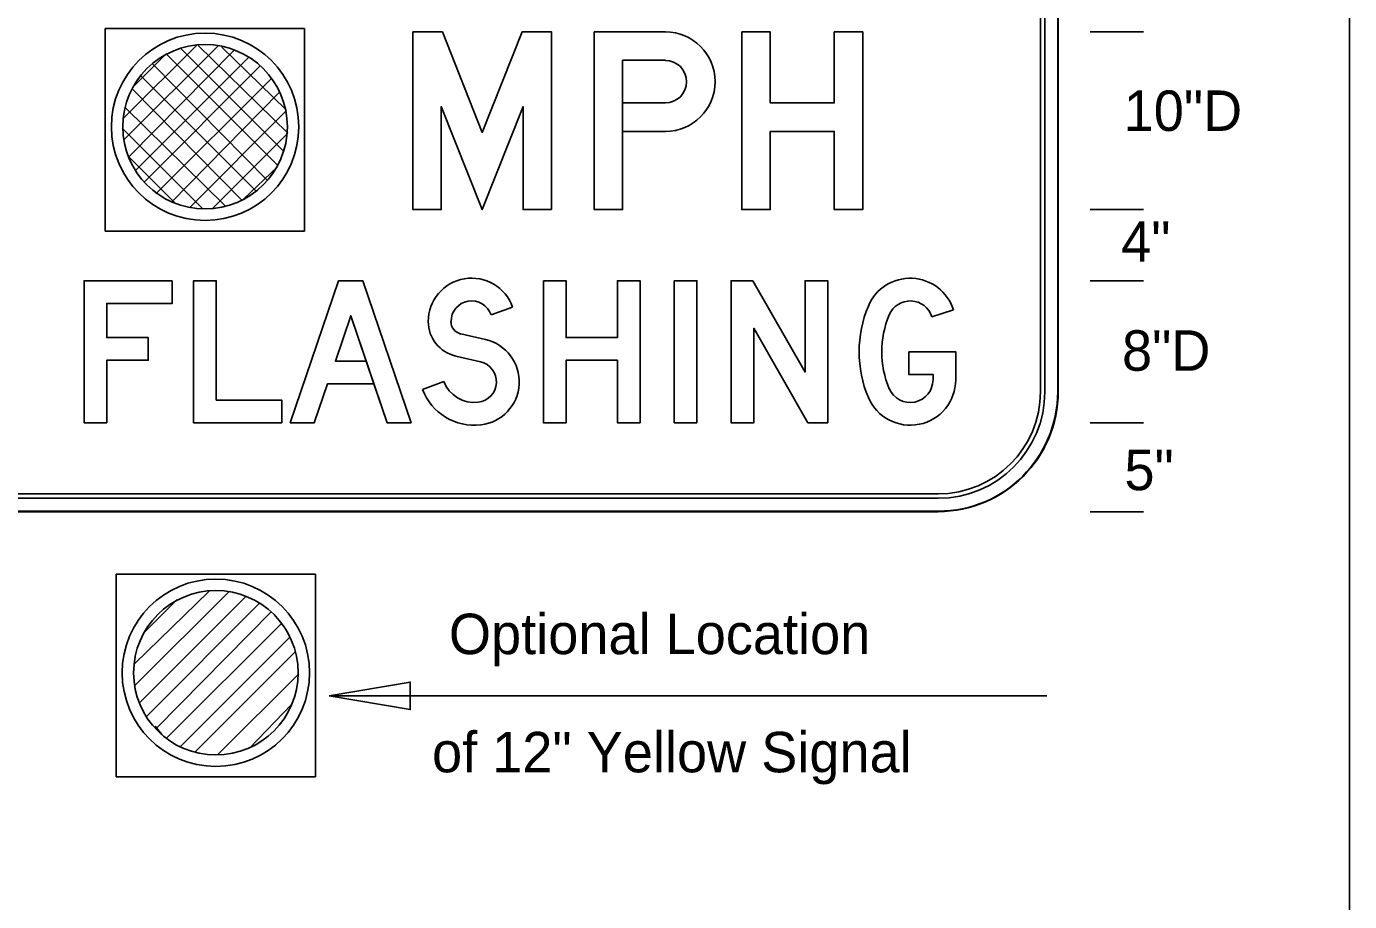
# Model space of a CAD drawing. Extents: x 0 to 770, y 0 to 495.
# Drawn here: x 463.1 to 577.5, y 359.7 to 435.4 of the extents above; entities that cross this region are included whole.
import ezdxf

# ---------------------------------------------------------------- set-up
doc = ezdxf.new("R2010")
doc.units = 0
for name, color, linetype in [('Default', 7, 'Continuous'), ('Dimension', 7, 'Continuous'), ('GSBWFill', 7, 'Continuous'), ('GSColorFill', 7, 'Continuous'), ('GSDims', 7, 'Continuous'), ('GSOutline', 7, 'Continuous'), ('SheetLines_dp', 7, 'Continuous'), ('TextStructures', 7, 'Continuous')]:
    doc.layers.add(name, color=color, linetype=linetype)

msp = doc.modelspace()

# ---------------------------------------------------------------- linework, layer by layer
at = {"layer": 'Default'}
for p, q in [((469.93, 435.23), (487.16, 435.23)), ((469.93, 417.71), (469.93, 435.23)), ((487.16, 417.71), (487.16, 435.23)), ((469.93, 417.71), (487.16, 417.71)), ((470.88, 388.03), (488.11, 388.03)), ((470.88, 370.51), (470.88, 388.03)), ((488.11, 370.51), (488.11, 388.03)), ((489.28, 377.52), (551.33, 377.52)), ((470.88, 370.51), (488.11, 370.51))]:
    msp.add_line(p, q, dxfattribs=at)
for points in [[(471.54, 425.6), (479.71, 433.77)], [(471.54, 427.49), (477.82, 433.77)], [(485.7, 426.18), (477.96, 433.77)], [(485.55, 428.22), (480.01, 433.62)], [(471.98, 424.14), (481.03, 433.33)], [(472.27, 430.12), (475.19, 433.04)], [(472.56, 422.97), (482.34, 432.75)], [(484.82, 423.41), (475.19, 433.04)], [(485.41, 424.57), (476.5, 433.48)], [(473.29, 421.95), (483.36, 432.02)], [(483.95, 422.09), (474.02, 432.16)], [(482.93, 421.22), (473, 431.14)], [(474.31, 420.92), (484.24, 430.85)], [(481.76, 420.34), (472.27, 429.98)], [(475.63, 420.19), (484.97, 429.68)], [(480.3, 419.9), (471.68, 428.37)], [(477.23, 419.76), (485.55, 428.08)], [(478.4, 419.61), (471.39, 426.62)], [(479.13, 419.61), (485.7, 426.18)], [(475.92, 420.19), (471.98, 424.14)], [(481.9, 420.49), (484.82, 423.26)], [(472.49, 378.4), (480.66, 386.57)], [(472.49, 380.3), (478.91, 386.57)], [(472.92, 376.94), (482.12, 386.14)], [(473.22, 382.92), (476.14, 385.84)], [(473.51, 375.77), (483.29, 385.55)], [(474.38, 374.75), (484.31, 384.82)], [(475.26, 373.87), (485.19, 383.8)], [(476.43, 373.14), (485.92, 382.63)], [(477.74, 372.7), (486.36, 381.32)], [(479.64, 372.41), (486.65, 379.42)], [(482.41, 373), (486.06, 376.79)], [(474.82, 374.16), (474.24, 374.89)]]:
    msp.add_lwpolyline(points, dxfattribs=at)
for centre, radius in [((478.56, 426.73), 8.1), ((478.56, 426.73), 7.11), ((479.49, 379.51), 8.1), ((479.49, 379.51), 7.11)]:
    msp.add_circle(centre, radius, dxfattribs=at)
at = {"layer": 'Dimension'}
msp.add_lwpolyline([(489.28, 377.52), (496.29, 376.33), (496.29, 378.71)], close=True, dxfattribs=at)
at = {"layer": 'GSBWFill'}
for p, q in [((550.77, 456.84), (550.77, 403.82)), ((551.16, 403.82), (551.16, 456.84)), ((552.31, 403.82), (552.31, 456.84)), ((514.66, 432.48), (518.35, 432.48)), ((503.28, 410.47), (505.14, 411.12)), ((541.4, 410.3), (543.27, 410.9)), ((502.8, 408.33), (500.68, 408.81)), ((500.24, 406.89), (502.36, 406.41)), ((499.2, 404.71), (497.36, 404.02)), ((541.94, 394.98), (415.16, 394.98)), ((415.16, 394.6), (541.94, 394.6)), ((415.15, 393.44), (541.94, 393.44))]:
    msp.add_line(p, q, dxfattribs=at)
for points in [[(508.51, 419.57), (508.51, 434.94), (505.97, 434.94), (502.52, 426.24), (499.07, 434.94), (496.53, 434.94), (496.53, 419.57), (498.98, 419.57), (498.98, 428.48), (502.52, 419.57), (506.05, 428.48), (506.05, 419.57)], [(524.96, 434.94), (527.42, 434.94), (527.42, 428.79), (532.95, 428.79), (532.95, 434.94), (535.41, 434.94), (535.41, 419.57), (532.95, 419.57), (532.95, 426.33), (527.42, 426.33), (527.42, 419.57), (524.96, 419.57)], [(475.72, 413.42), (475.72, 411.45), (470.06, 411.45), (470.06, 408.5), (473.64, 408.5), (473.64, 406.54), (470.06, 406.54), (470.06, 401.13), (468.1, 401.13), (468.1, 413.42)], [(479.53, 403.09), (485.18, 403.09), (485.18, 401.13), (477.56, 401.13), (477.56, 413.42), (479.53, 413.42)], [(485.92, 401.13), (490.1, 413.42), (492.19, 413.42), (496.37, 401.13), (494.29, 401.13), (491.15, 410.38), (489.82, 406.47), (492.48, 406.47), (493.14, 404.51), (489.15, 404.51), (488, 401.13)], [(507.81, 413.42), (509.77, 413.42), (509.77, 408.5), (514.2, 408.5), (514.2, 413.42), (516.17, 413.42), (516.17, 401.13), (514.2, 401.13), (514.2, 406.54), (509.77, 406.54), (509.77, 401.13), (507.81, 401.13)], [(519.12, 413.42), (521.08, 413.42), (521.08, 401.13), (519.12, 401.13)], [(532.39, 401.13), (532.39, 413.42), (530.43, 413.42), (530.43, 405.52), (525.91, 413.42), (524.03, 413.42), (524.03, 401.13), (526, 401.13), (526, 409.3), (530.67, 401.13)]]:
    msp.add_lwpolyline(points, close=True, dxfattribs=at)
for points in [[(518.35, 434.94), (512.2, 434.94), (512.2, 419.57), (514.66, 419.57), (514.66, 432.48)], [(518.35, 428.79), (514.66, 428.79), (514.66, 426.33), (518.35, 426.33)], [(539.4, 407.27), (539.4, 405.31), (541.49, 405.31), (541.49, 404.85)], [(543.46, 404.85), (543.46, 407.27), (539.4, 407.27)]]:
    msp.add_lwpolyline(points, dxfattribs=at)
for centre, radius, start, end in [((518.35, 430.63), 4.3, 270, 90), ((518.35, 430.63), 1.84, 270, 90), ((539.52, 409.7), 3.93, 17.7394, 157.1013), ((545.27, 407.27), 10.17, 157.1013, 202.8987), ((539.52, 409.7), 1.97, 17.7394, 157.1013), ((545.27, 407.27), 8.21, 157.1013, 202.8987), ((539.52, 404.85), 3.93, 202.8987, 0), ((539.52, 404.85), 1.97, 202.8987, 0), ((541.94, 403.82), 9.22, 270, 0), ((541.94, 403.82), 8.84, 270, 0), ((541.94, 403.82), 10.37, 270, 0)]:
    msp.add_arc(centre, radius, start, end, dxfattribs=at)
for centre, major_axis, start_param, end_param in [((501.6, 409.89), (0, 3.75), 5.046436, 7.853982), ((501.6, 409.89), (0, 1.78), 5.046436, 7.853982), ((500.92, 409.89), (0, 3.07), 1.570796, 2.918042), ((500.92, 409.89), (0, 1.11), 1.570796, 2.918042), ((501.97, 404.67), (0, 3.75), 3.26002, 6.059635), ((501.97, 404.67), (0, 1.78), 3.26002, 6.059635), ((501.84, 405.71), (0, 4.79), 1.931106, 3.26002), ((501.84, 405.71), (0, 2.83), 1.931106, 3.26002)]:
    msp.add_ellipse(centre, major_axis=major_axis, ratio=0.999993, start_param=start_param, end_param=end_param, dxfattribs=at)
at = {"layer": 'GSColorFill'}
for p, q in [((550.77, 456.84), (550.77, 403.82)), ((551.16, 403.82), (551.16, 456.84)), ((552.27, 456.84), (552.27, 403.82)), ((552.31, 403.82), (552.31, 456.84)), ((552.31, 403.82), (552.31, 456.84)), ((514.66, 432.48), (518.35, 432.48)), ((503.28, 410.47), (505.14, 411.12)), ((541.4, 410.3), (543.27, 410.9)), ((502.8, 408.33), (500.68, 408.81)), ((500.24, 406.89), (502.36, 406.41)), ((499.2, 404.71), (497.36, 404.02)), ((541.94, 394.98), (415.16, 394.98)), ((541.94, 393.48), (415.15, 393.48)), ((415.16, 394.6), (541.94, 394.6)), ((415.15, 393.44), (541.94, 393.44)), ((415.15, 393.44), (541.94, 393.44))]:
    msp.add_line(p, q, dxfattribs=at)
for points in [[(508.51, 419.57), (508.51, 434.94), (505.97, 434.94), (502.52, 426.24), (499.07, 434.94), (496.53, 434.94), (496.53, 419.57), (498.98, 419.57), (498.98, 428.48), (502.52, 419.57), (506.05, 428.48), (506.05, 419.57)], [(524.96, 434.94), (527.42, 434.94), (527.42, 428.79), (532.95, 428.79), (532.95, 434.94), (535.41, 434.94), (535.41, 419.57), (532.95, 419.57), (532.95, 426.33), (527.42, 426.33), (527.42, 419.57), (524.96, 419.57)], [(475.72, 413.42), (475.72, 411.45), (470.06, 411.45), (470.06, 408.5), (473.64, 408.5), (473.64, 406.54), (470.06, 406.54), (470.06, 401.13), (468.1, 401.13), (468.1, 413.42)], [(479.53, 403.09), (485.18, 403.09), (485.18, 401.13), (477.56, 401.13), (477.56, 413.42), (479.53, 413.42)], [(485.92, 401.13), (490.1, 413.42), (492.19, 413.42), (496.37, 401.13), (494.29, 401.13), (491.15, 410.38), (489.82, 406.47), (492.48, 406.47), (493.14, 404.51), (489.15, 404.51), (488, 401.13)], [(507.81, 413.42), (509.77, 413.42), (509.77, 408.5), (514.2, 408.5), (514.2, 413.42), (516.17, 413.42), (516.17, 401.13), (514.2, 401.13), (514.2, 406.54), (509.77, 406.54), (509.77, 401.13), (507.81, 401.13)], [(519.12, 413.42), (521.08, 413.42), (521.08, 401.13), (519.12, 401.13)], [(532.39, 401.13), (532.39, 413.42), (530.43, 413.42), (530.43, 405.52), (525.91, 413.42), (524.03, 413.42), (524.03, 401.13), (526, 401.13), (526, 409.3), (530.67, 401.13)]]:
    msp.add_lwpolyline(points, close=True, dxfattribs=at)
for points in [[(518.35, 434.94), (512.2, 434.94), (512.2, 419.57), (514.66, 419.57), (514.66, 432.48)], [(518.35, 428.79), (514.66, 428.79), (514.66, 426.33), (518.35, 426.33)], [(539.4, 407.27), (539.4, 405.31), (541.49, 405.31), (541.49, 404.85)], [(543.46, 404.85), (543.46, 407.27), (539.4, 407.27)]]:
    msp.add_lwpolyline(points, dxfattribs=at)
for centre, radius, start, end in [((518.35, 430.63), 4.3, 270, 90), ((518.35, 430.63), 1.84, 270, 90), ((539.52, 409.7), 3.93, 17.7394, 157.1013), ((545.27, 407.27), 10.17, 157.1013, 202.8987), ((539.52, 409.7), 1.97, 17.7394, 157.1013), ((545.27, 407.27), 8.21, 157.1013, 202.8987), ((539.52, 404.85), 3.93, 202.8987, 0), ((539.52, 404.85), 1.97, 202.8987, 0), ((541.94, 403.82), 10.37, 270, 0), ((541.94, 403.82), 9.22, 270, 0), ((541.94, 403.82), 8.84, 270, 0), ((541.94, 403.82), 10.37, 270, 0), ((541.94, 403.82), 10.33, 270, 0)]:
    msp.add_arc(centre, radius, start, end, dxfattribs=at)
for centre, major_axis, start_param, end_param in [((501.6, 409.89), (0, 3.75), 5.046436, 7.853982), ((501.6, 409.89), (0, 1.78), 5.046436, 7.853982), ((500.92, 409.89), (0, 3.07), 1.570796, 2.918042), ((500.92, 409.89), (0, 1.11), 1.570796, 2.918042), ((501.97, 404.67), (0, 3.75), 3.26002, 6.059635), ((501.97, 404.67), (0, 1.78), 3.26002, 6.059635), ((501.84, 405.71), (0, 4.79), 1.931106, 3.26002), ((501.84, 405.71), (0, 2.83), 1.931106, 3.26002)]:
    msp.add_ellipse(centre, major_axis=major_axis, ratio=0.999993, start_param=start_param, end_param=end_param, dxfattribs=at)
at = {"layer": 'GSDims'}
for p, q in [((555.08, 434.94), (559.69, 434.94)), ((555.08, 434.94), (559.69, 434.94)), ((555.08, 419.57), (559.69, 419.57)), ((555.08, 419.57), (559.69, 419.57)), ((555.08, 413.42), (559.69, 413.42)), ((555.08, 413.42), (559.69, 413.42)), ((555.08, 401.13), (559.69, 401.13)), ((555.08, 401.13), (559.69, 401.13)), ((555.08, 393.44), (559.69, 393.44))]:
    msp.add_line(p, q, dxfattribs=at)
at = {"layer": 'GSOutline'}
for p, q in [((550.77, 403.82), (550.77, 456.84)), ((551.16, 403.82), (551.16, 456.84)), ((552.31, 403.82), (552.31, 456.84)), ((514.66, 426.33), (518.35, 426.33)), ((503.28, 410.47), (505.14, 411.12)), ((541.4, 410.3), (543.27, 410.9)), ((502.8, 408.33), (500.68, 408.81)), ((500.24, 406.89), (502.36, 406.41)), ((499.2, 404.71), (497.36, 404.02)), ((415.15, 394.98), (541.94, 394.98)), ((415.15, 394.6), (541.94, 394.6)), ((415.15, 393.44), (541.94, 393.44))]:
    msp.add_line(p, q, dxfattribs=at)
for points in [[(508.51, 419.57), (508.51, 434.94), (505.97, 434.94), (502.52, 426.24), (499.07, 434.94), (496.53, 434.94), (496.53, 419.57), (498.98, 419.57), (498.98, 428.48), (502.52, 419.57), (506.05, 428.48), (506.05, 419.57)], [(524.96, 434.94), (527.42, 434.94), (527.42, 428.79), (532.95, 428.79), (532.95, 434.94), (535.41, 434.94), (535.41, 419.57), (532.95, 419.57), (532.95, 426.33), (527.42, 426.33), (527.42, 419.57), (524.96, 419.57)], [(475.72, 413.42), (475.72, 411.45), (470.06, 411.45), (470.06, 408.5), (473.64, 408.5), (473.64, 406.54), (470.06, 406.54), (470.06, 401.13), (468.1, 401.13), (468.1, 413.42)], [(479.53, 403.09), (485.18, 403.09), (485.18, 401.13), (477.56, 401.13), (477.56, 413.42), (479.53, 413.42)], [(489.15, 404.51), (488, 401.13), (485.92, 401.13), (490.1, 413.42), (492.19, 413.42), (496.37, 401.13), (494.29, 401.13), (493.15, 404.51)], [(507.81, 413.42), (509.77, 413.42), (509.77, 408.5), (514.2, 408.5), (514.2, 413.42), (516.17, 413.42), (516.17, 401.13), (514.2, 401.13), (514.2, 406.54), (509.77, 406.54), (509.77, 401.13), (507.81, 401.13)], [(519.12, 413.42), (521.08, 413.42), (521.08, 401.13), (519.12, 401.13)], [(532.39, 401.13), (532.39, 413.42), (530.43, 413.42), (530.43, 405.52), (525.91, 413.42), (524.03, 413.42), (524.03, 401.13), (526, 401.13), (526, 409.3), (530.67, 401.13)], [(489.82, 406.47), (492.48, 406.47), (491.15, 410.38)]]:
    msp.add_lwpolyline(points, close=True, dxfattribs=at)
for points in [[(518.35, 434.94), (512.2, 434.94), (512.2, 419.57), (514.66, 419.57), (514.66, 426.33)], [(518.35, 428.79), (514.66, 428.79), (514.66, 432.48), (518.35, 432.48)], [(539.4, 407.27), (539.4, 405.31), (541.49, 405.31), (541.49, 404.85)], [(543.46, 404.85), (543.46, 407.27), (539.4, 407.27)]]:
    msp.add_lwpolyline(points, dxfattribs=at)
for centre, radius, start, end in [((518.35, 430.63), 4.3, 270, 90), ((518.35, 430.63), 1.84, 270, 90), ((539.52, 409.7), 3.93, 17.7394, 157.1013), ((545.27, 407.27), 10.17, 157.1013, 202.8987), ((539.52, 409.7), 1.97, 17.7394, 157.1013), ((545.27, 407.27), 8.21, 157.1013, 202.8987), ((539.52, 404.85), 3.93, 202.8987, 0), ((539.52, 404.85), 1.97, 202.8987, 0), ((541.94, 403.82), 9.22, 270, 0), ((541.94, 403.82), 8.84, 270, 0), ((541.94, 403.82), 10.37, 270, 0)]:
    msp.add_arc(centre, radius, start, end, dxfattribs=at)
for centre, major_axis, start_param, end_param in [((501.6, 409.89), (0, 3.75), 5.046436, 7.853982), ((501.6, 409.89), (0, 1.78), 5.046436, 7.853982), ((500.92, 409.89), (0, 3.07), 1.570796, 2.918042), ((500.92, 409.89), (0, 1.11), 1.570796, 2.918042), ((501.97, 404.67), (0, 3.75), 3.26002, 6.059635), ((501.97, 404.67), (0, 1.78), 3.26002, 6.059635), ((501.84, 405.71), (0, 4.79), 1.931106, 3.26002), ((501.84, 405.71), (0, 2.83), 1.931106, 3.26002)]:
    msp.add_ellipse(centre, major_axis=major_axis, ratio=0.999993, start_param=start_param, end_param=end_param, dxfattribs=at)
at = {"layer": 'SheetLines_dp'}
msp.add_line((577.5, 0), (577.5, 495), dxfattribs=at)

# ---------------------------------------------------------------- texts
at = {"layer": 'TextStructures'}
for s, p in [('10"D', (557.97, 426.37)), ('4"', (557.76, 415.06)), ('8"D', (557.83, 405.63)), ('5"', (558.04, 395.3))]:
    msp.add_text(s, height=3.5, dxfattribs=at).set_placement(p)
for s, p in [('Optional Location', (499.64, 381.12)), ('of 12" Yellow Signal', (498.18, 370.9))]:
    msp.add_text(s, height=3.5, rotation=0, dxfattribs=at).set_placement(p)

doc.saveas('drawing.dxf')
